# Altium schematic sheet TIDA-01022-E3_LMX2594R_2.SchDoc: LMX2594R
size 431 x 279 mm; Date: Not shown in title block; ApprovedBy: Not shown in title block; CheckedBy: Not shown in title block; Author: Not shown in title block; CompanyName: Not shown in title block; DrawnBy: Avinash N; Engineer: Not shown in title block; Organization: Not shown in title block; Address1: Not shown in title block; Address2: Not shown in title block; Address3: Not shown in title block; Address4: Not shown in title block; DocumentNumber: 1; Revision: Use project parameter SCH_Rev; SheetNumber: 11; SheetTotal: 26; PageSetup: Record=PageOptions¦CenterHorizontal=True¦CenterVertical=True¦PrintScale=0.59¦XCorrection=1.00¦YCorrection=1.00¦PrintKind=0¦BorderSize=5000000¦LeftOffset=0¦BottomOffset=0¦Orientation=2¦PaperLength=1000¦PaperWidth=1000¦Scale=100¦PaperSource=15¦PrintQuality=600¦MediaType=1¦DitherType=10¦PrintScaleMode=1¦PaperKind=Letter
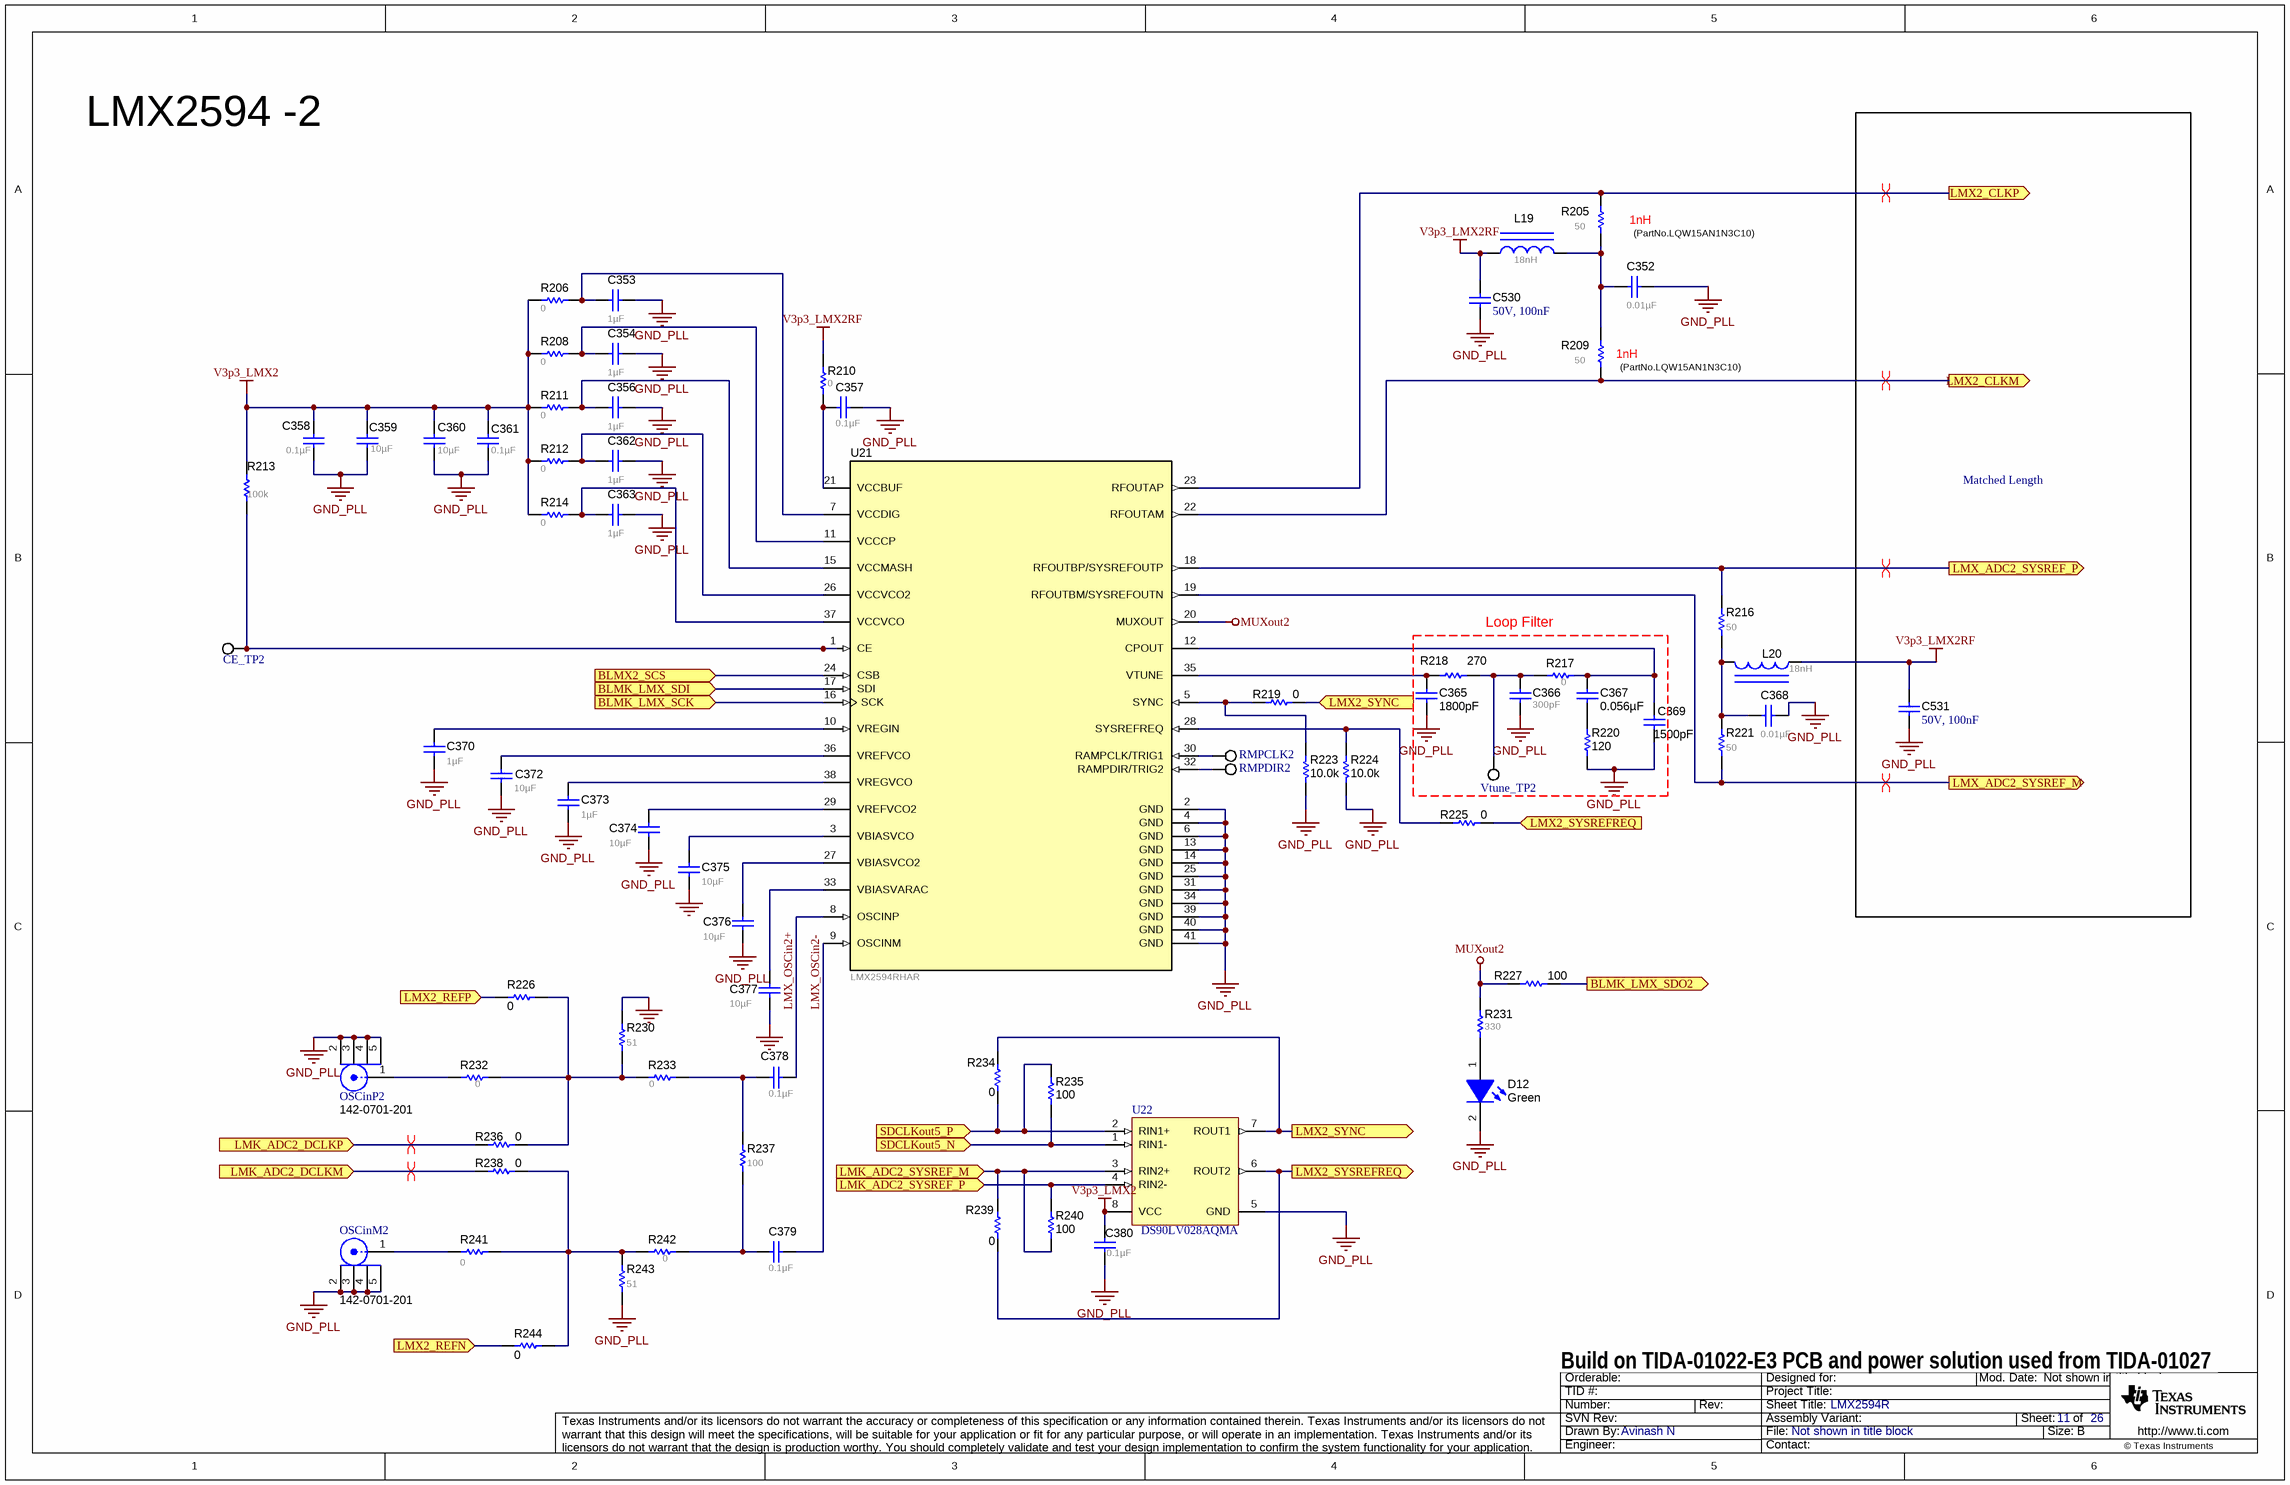
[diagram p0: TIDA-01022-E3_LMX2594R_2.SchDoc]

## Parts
C352  ValueDisplayed: 0.01µF  [0402_065]  (hidden comment: 520L103KT16T)
C353  ValueDisplayed: 1µF  [0603]  (hidden comment: C1608X7R1C105K080AC)
C354  ValueDisplayed: 1µF  [0603L]  (hidden comment: C1608X7R1C105K080AC)
C356  ValueDisplayed: 1µF  [0603L]  (hidden comment: C1608X7R1C105K080AC)
C357  ValueDisplayed: 0.1µF  [0603L]  (hidden comment: 0603YC104JAT2A)
C358  ValueDisplayed: 0.1µF  [0603]  (hidden comment: 0603YC104JAT2A)
C359  ValueDisplayed: 10µF  [0805]  (hidden comment: C0805C106K8PACTU)
C360  ValueDisplayed: 10µF  [0805]  (hidden comment: C0805C106K8PACTU)
C361  ValueDisplayed: 0.1µF  [0603]  (hidden comment: 0603YC104JAT2A)
C362  ValueDisplayed: 1µF  [0603]  (hidden comment: C1608X7R1C105K080AC)
C363  ValueDisplayed: 1µF  [0603]  (hidden comment: C1608X7R1C105K080AC)
C365  ValueDisplayed: 1800pF  [0603]  (hidden comment: GRM1885C1H182JA01D)
C366  ValueDisplayed: 300pF  [0603]  (hidden comment: GRM1885C2A301JA01D)
C367  ValueDisplayed: 0.056µF  [0603]  (hidden comment: C0603C563J4RACTU)
C368  ValueDisplayed: 0.01µF  [0402_065]  (hidden comment: 520L103KT16T)
C369  ValueDisplayed: 1500pF  [0603]  (hidden comment: 06031C152JAT2A)
C370  ValueDisplayed: 1µF  [0603]  (hidden comment: C1608X7R1C105K080AC)
C372  ValueDisplayed: 10µF  [0603]  (hidden comment: C1608X5R1A106M080AC)
C373  ValueDisplayed: 1µF  [0603]  (hidden comment: C1608X7R1C105K080AC)
C374  ValueDisplayed: 10µF  [0603]  (hidden comment: C1608X5R1A106M080AC)
C375  ValueDisplayed: 10µF  [0603]  (hidden comment: C1608X5R1A106M080AC)
C376  ValueDisplayed: 10µF  [0603]  (hidden comment: C1608X5R1A106M080AC)
C377  ValueDisplayed: 10µF  [0603]  (hidden comment: C1608X5R1A106M080AC)
C378  ValueDisplayed: 0.1µF  [0603L]  (hidden comment: 0603YC104JAT2A)
C379  ValueDisplayed: 0.1µF  [0603L]  (hidden comment: 0603YC104JAT2A)
C380  ValueDisplayed: 0.1µF  [0603]  (hidden comment: 0603YC104JAT2A)
C530  50V, 100nF  [0603_1.6x0.8x0.8mm_Reflow Soldering]
C531  50V, 100nF  [0603_1.6x0.8x0.8mm_Reflow Soldering]
CE_TP2  5002  [Keystone5002]  (value not drawn)
D12  value Green  [LTST-C191_Green]  (hidden comment: LTST-C191TGKT)
L19  ValueDisplayed: 18nH  [IND_LQG15H]  (hidden comment: LQG15HS18NJ02D)
L20  ValueDisplayed: 18nH  [IND_LQG15H]  (hidden comment: LQG15HS18NJ02D)
OSCinM2  142-0701-201  [Johnson_142-0701-20x]
OSCinP2  142-0701-201  [Johnson_142-0701-20x]
R205  ValueDisplayed: 50  [0402L]  (hidden comment: FC0402E50R0BST1)
R206  value 0  [0603]  (hidden comment: CRCW06030000Z0EA)
R208  value 0  [0603L]  (hidden comment: CRCW06030000Z0EA)
R209  ValueDisplayed: 50  [0402L]  (hidden comment: FC0402E50R0BST1)
R210  value 0  [0603L]  (hidden comment: CRCW06030000Z0EA)
R211  value 0  [0603L]  (hidden comment: CRCW06030000Z0EA)
R212  value 0  [0603]  (hidden comment: CRCW06030000Z0EA)
R213  ValueDisplayed: 100k  [0603]  (hidden comment: CRCW0603100KJNEA)
R214  value 0  [0603]  (hidden comment: CRCW06030000Z0EA)
R216  ValueDisplayed: 50  [0402L]  (hidden comment: FC0402E50R0BST1)
R217  ValueDisplayed: 0  [0603]  (hidden comment: CRCW06030000Z0EA)
R218  ValueDisplayed: 270  [0603]  (hidden comment: RC0603JR-07270RL)
R219  ValueDisplayed: 0  [0402]  (hidden comment: CRCW04020000Z0ED)
R220  ValueDisplayed: 120  [0603]  (hidden comment: RT0603DRE07120RL)
R221  ValueDisplayed: 50  [0402L]  (hidden comment: FC0402E50R0BST1)
R223  ValueDisplayed: 10.0k  [0402]  (hidden comment: CRCW040210K0DHEDP)
R224  ValueDisplayed: 10.0k  [0402]  (hidden comment: CRCW040210K0DHEDP)
R225  ValueDisplayed: 0  [0402]  (hidden comment: CRCW04020000Z0ED)
R226  ValueDisplayed: 0  [0402]  (hidden comment: CRCW04020000Z0ED)
R227  ValueDisplayed: 100  [0603]  (hidden comment: CRCW0603100RFKEA)
R230  ValueDisplayed: 51  [0603]  (hidden comment: CRCW060351R0JNEA)
R231  value 330  [0603]  (hidden comment: RC0603JR-07330RL)
R232  ValueDisplayed: 0  [0603]  (hidden comment: CRCW06030000Z0EA)
R233  ValueDisplayed: 0  [0603]  (hidden comment: CRCW06030000Z0EA)
R234  ValueDisplayed: 0  [0402]  (hidden comment: CRCW04020000Z0ED)
R235  ValueDisplayed: 100  [0402]  (hidden comment: CRCW0402100RJNED)
R236  ValueDisplayed: 0  [0402]  (hidden comment: CRCW04020000Z0ED)
R237  ValueDisplayed: 100  [0603L]  (hidden comment: CRCW0603100RFKEA)
R238  ValueDisplayed: 0  [0402]  (hidden comment: CRCW04020000Z0ED)
R239  ValueDisplayed: 0  [0402]  (hidden comment: CRCW04020000Z0ED)
R240  ValueDisplayed: 100  [0402]  (hidden comment: CRCW0402100RJNED)
R241  ValueDisplayed: 0  [0603]  (hidden comment: CRCW06030000Z0EA)
R242  ValueDisplayed: 0  [0603]  (hidden comment: CRCW06030000Z0EA)
R243  ValueDisplayed: 51  [0603]  (hidden comment: CRCW060351R0JNEA)
R244  ValueDisplayed: 0  [0402]  (hidden comment: CRCW04020000Z0ED)
RMPCLK2  5002  [Keystone5002]  (value not drawn)
RMPDIR2  5002  [Keystone5002]  (value not drawn)
U21  LMX2594RHAR  [RHA0040A]
U22  DS90LV028AQMA  [M08A_N]
Vtune_TP2  5002  [Keystone5002]  (value not drawn)

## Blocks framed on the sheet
Matched Length: C531
Loop Filter: C365-C367 C369 R217 R218 R220 Vtune_TP2

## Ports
BLMK_LMX_SCK (in), BLMK_LMX_SDI (in), BLMK_LMX_SDO2 (out), BLMX2_SCS (in), LMK_ADC2_DCLKM (in), LMK_ADC2_DCLKP (in), LMK_ADC2_SYSREF_M (in), LMK_ADC2_SYSREF_P (in), LMX2_CLKM (out), LMX2_CLKP (out), LMX2_REFN (in), LMX2_REFP (in), LMX2_SYNC (in), LMX2_SYNC (out), LMX2_SYSREFREQ (in), LMX2_SYSREFREQ (out), LMX_ADC2_SYSREF_M (out), LMX_ADC2_SYSREF_P (out), SDCLKout5_N (in), SDCLKout5_P (in)

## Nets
GND_PLL: C352.1 C353.1 C354.1 C356.2 C357.1 C358.1 C359.1 C360.1 C361.1 C362.1 C363.1 C365.1 C366.2 C368.1 C369.2 C370.1 C372.2 C373.1 C374.2 C375.2 C376.1 C377.1 C380.1 C530.2 C531.2 D12.2(K) OSCinM2.2 OSCinM2.3 OSCinM2.4 OSCinM2.5 OSCinP2.2 OSCinP2.3 OSCinP2.4 OSCinP2.5 R220.2 R223.2 R224.2 R230.2 R243.1 U21.2(GND) U21.4(GND) U21.6(GND) U21.13(GND) U21.14(GND) U21.25(GND) U21.31(GND) U21.34(GND) U21.39(GND) U21.40(GND) U21.41(GND) U22.5(GND)
MUXout2: R227.1 R231.2 U21.20(MUXOUT)
V3p3_LMX2: C358.2 C359.2 C360.2 C361.2 C380.2 R206.1 R208.1 R211.1 R212.2 R213.1 R214.2 U22.8(VCC)
V3p3_LMX2RF: C530.1 C531.1 L19.1 L20.1 R210.1
BLMK_LMX_SCK: U21.16(SCK) ; port BLMK_LMX_SCK
BLMK_LMX_SDI: U21.17(SDI) ; port BLMK_LMX_SDI
BLMK_LMX_SDO2: R227.2 ; port BLMK_LMX_SDO2
BLMX2_SCS: U21.24(CSB) ; port BLMX2_SCS
LMK_ADC2_DCLKM: R238.1 ; port LMK_ADC2_DCLKM
LMK_ADC2_DCLKP: R236.1 ; port LMK_ADC2_DCLKP
LMK_ADC2_SYSREF_M: R239.1 R240.1 U22.3(RIN2+) ; port LMK_ADC2_SYSREF_M
LMK_ADC2_SYSREF_P: R240.2 U22.4(RIN2-) ; port LMK_ADC2_SYSREF_P
LMX2_CLKM: R209.1 U21.22(RFOUTAM) ; port LMX2_CLKM
LMX2_CLKP: R205.1 U21.23(RFOUTAP) ; port LMX2_CLKP
LMX2_REFN: R244.1 ; port LMX2_REFN
LMX2_REFP: R226.2 ; port LMX2_REFP
LMX2_SYNC: R219.2 R234.1 U22.7(ROUT1) ; port LMX2_SYNC
LMX2_SYSREFREQ: R225.2 R239.2 U22.6(ROUT2) ; port LMX2_SYSREFREQ
LMX_ADC2_SYSREF_M: R221.1 U21.19(RFOUTBM/SYSREFOUTN) ; port LMX_ADC2_SYSREF_M
LMX_ADC2_SYSREF_P: R216.2 U21.18(RFOUTBP/SYSREFOUTP) ; port LMX_ADC2_SYSREF_P
LMX_OSCin2+: C378.2 U21.8(OSCINP)
LMX_OSCin2-: C379.2 U21.9(OSCINM)
SDCLKout5_N: R235.1 U22.1(RIN1-) ; port SDCLKout5_N
SDCLKout5_P: R234.2 R235.2 U22.2(RIN1+) ; port SDCLKout5_P
NetC352_2: C352.2 L19.2 R205.2 R209.2
NetC353_2: C353.2 R206.2 U21.7(VCCDIG)
NetC354_2: C354.2 R208.2 U21.11(VCCCP)
NetC356_1: C356.1 R211.2 U21.15(VCCMASH)
NetC357_2: C357.2 R210.2 U21.21(VCCBUF)
NetC362_2: C362.2 R212.1 U21.26(VCCVCO2)
NetC363_2: C363.2 R214.1 U21.37(VCCVCO)
NetC365_2: C365.2 R218.1 U21.35(VTUNE)
NetC366_1: C366.1 R217.2 R218.2 Vtune_TP2.1
NetC367_1: C367.1 C369.1 R217.1 U21.12(CPOUT)
NetC367_2: C367.2 R220.1
NetC368_2: C368.2 L20.2 R216.1 R221.2
NetC370_2: C370.2 U21.10(VREGIN)
NetC372_1: C372.1 U21.36(VREFVCO)
NetC373_2: C373.2 U21.38(VREGVCO)
NetC374_1: C374.1 U21.29(VREFVCO2)
NetC375_1: C375.1 U21.3(VBIASVCO)
NetC376_2: C376.2 U21.27(VBIASVCO2)
NetC377_2: C377.2 U21.33(VBIASVARAC)
NetC378_1: C378.1 R233.2 R237.2
NetC379_1: C379.1 R237.1 R242.1
NetCE_TP2_1: CE_TP2.1 R213.2 U21.1(CE)
NetD12_1: D12.1(A) R231.1
NetOSCinM2_1: OSCinM2.1 R241.1
NetOSCinP2_1: OSCinP2.1 R232.1
NetR219_1: R219.1 R223.1 U21.5(SYNC)
NetR224_1: R224.1 R225.1 U21.28(SYSREFREQ)
NetR226_1: R226.1 R230.1 R232.2 R233.1 R236.2
NetR238_2: R238.2 R241.2 R242.2 R243.2 R244.2
NetRMPCLK2_1: RMPCLK2.1 U21.30(RAMPCLK/TRIG1)
NetRMPDIR2_1: RMPDIR2.1 U21.32(RAMPDIR/TRIG2)

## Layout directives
differential pair: LMK_ADC2_DCLKM, LMK_ADC2_DCLKP, LMX2_CLKM, LMX2_CLKP, LMX_ADC2_SYSREF_M, LMX_ADC2_SYSREF_P

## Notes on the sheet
- LMX2594 -2
- (near R205) 1nH
- (PartNo.LQW15AN1N3C10)
- (near R209) 1nH
- (near R209) (PartNo.LQW15AN1N3C10)
- Build on TIDA-01022-E3 PCB and power solution used from TIDA-01027

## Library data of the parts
C352 C368 = 520L103KT16T: CAP, CERM, 0.01 µF, 16 V, +/- 10%, X7R, 0402; Manufacturer: AT Ceramics; Polarized: N; CompType: Capacitor; Value: 0.01uF; U/M: EA; Cap_F: 0.00000001; Tolerance_%: 10; Value1: Unknown; VDC_V: 16; Value2: 16V; TaMin_C: -55; TaMax_C: 125; Cap_Case: 0402; AEC Category: Q200; SizeArea_mm2: 0.5; SizeAreaWB_mm2: 3; SizeX_mm: 1; SizeZ_mm: 0.65
C353 C362 C363 = C1608X7R1C105K080AC: CAP, CERM, 1 µF, 16 V, +/- 10%, X7R, 0603; Manufacturer: TDK; ESR_ohm: 0.0057; Polarized: N; TaMax_C: 125; TaMin_C: -55; Tolerance_%: 10; VDC_V: 16; Cap_F: 0.000001; CompType: Capacitor; Value: 1uF; Value1: 0.0057 ohm; Value2: 16V; U/M: EA; SizeArea_mm2: 1.28; SizeAreaWB_mm2: 4.68; SizeX_mm: 1.6; SizeY_mm: 0.8; SizeZ_mm: 1; AEC Category: Q200
C354 C356 = C1608X7R1C105K080AC: CAP, CERM, 1 µF, 16 V, +/- 10%, X7R, 0603; Manufacturer: TDK; Cap_Case: 0603; ESR_ohm: 0.0057; Polarized: N; TaMax_C: 125; TaMin_C: -55; Tolerance_%: 10; VDC_V: 16; Cap_F: 0.000001; CompType: Capacitor; Value: 1uF; Value1: 0.0057 ohm; Value2: 16V; U/M: EA; SizeArea_mm2: 1.28; SizeAreaWB_mm2: 4.68; SizeX_mm: 1.6; SizeY_mm: 0.8; SizeZ_mm: 1; AEC Category: Q200
C357 C378 C379 = 0603YC104JAT2A: CAP, CERM, 0.1uF, 16V, +/-5%, X7R, 0603; Manufacturer: AVX; Cap_Case: 0603; ESR_Ohm: 0.039; Polarized: N; TaMax_C: 125; TaMin_C: -55; Tolerance_%: 5; VDC_V: 16; Cap_F: 0.0000001; CompType: Capacitor; Value1: 0.039 ohm; U/M: EA
C358 C361 C380 = 0603YC104JAT2A: CAP, CERM, 0.1uF, 16V, +/-5%, X7R, 0603; Manufacturer: AVX; ESR_Ohm: 0.039; Polarized: N; TaMax_C: 125; TaMin_C: -55; Tolerance_%: 5; VDC_V: 16; Cap_F: 0.0000001; CompType: Capacitor; Value1: 0.039 ohm; U/M: EA
C359 C360 = C0805C106K8PACTU: CAP, CERM, 10uF, 10V, +/-10%, X5R, 0805; Manufacturer: Kemet; ESR_Ohm: 0.003; IRMS_A: 11.43; Polarized: N; TaMax_C: 85; TaMin_C: -55; Tolerance_%: 10; Cap_F: 0.00001; CompType: Capacitor; U/M: EA; Value1: 0.003 ohm
C365 = GRM1885C1H182JA01D: CAP, CERM, 1800 pF, 50 V, +/- 5%, C0G/NP0, 0603; Manufacturer: MuRata; Polarized: N; TaMax_C: 125; TaMin_C: -55; Tolerance_%: 5; VDC_V: 50; Cap_F: 0.0000000018; CompType: Capacitor; Value: 1800pF; Value1: Unknown; Value2: 50V; U/M: EA; SizeArea_mm2: 1.28; SizeAreaWB_mm2: 4.68; SizeX_mm: 1.6; SizeY_mm: 0.8; SizeZ_mm: 1; AEC Category: Q200
C366 = GRM1885C2A301JA01D: CAP, CERM, 300pF, 100V, +/-5%, C0G/NP0, 0603; Manufacturer: MuRata; Polarized: N; TaMax_C: 125; TaMin_C: -55; Tolerance_%: 5; VDC_V: 100; Cap_F: 0.0000000003; CompType: Capacitor; Value1: Unknown; U/M: EA
C367 = C0603C563J4RACTU: CAP, CERM, 0.056 µF, 16 V, +/- 5%, X7R, 0603; Manufacturer: Kemet; Polarized: N; TaMax_C: 125; TaMin_C: -55; Tolerance_%: 5; VDC_V: 16; Cap_F: 0.000000056; CompType: Capacitor; Value: 0.056uF; Value1: Unknown; Value2: 16V; U/M: EA; AEC Category: Q200; SizeArea_mm2: 1.28; SizeAreaWB_mm2: 4.68; SizeX_mm: 1.6; SizeY_mm: 0.8; SizeZ_mm: 1
C369 = 06031C152JAT2A: CAP, CERM, 1500 pF, 100 V, +/- 5%, X7R, 0603; Manufacturer: AVX; ESR_ohm: 0.229; Polarized: N; TaMax_C: 125; TaMin_C: -55; Tolerance_%: 5; VDC_V: 100; Cap_F: 0.0000000015; CompType: Capacitor; Value: 1500pF; Value1: 0.229 ohm; Value2: 100V; U/M: EA; AEC Category: Q200; SizeArea_mm2: 1.28; SizeAreaWB_mm2: 4.68; SizeX_mm: 1.6; SizeY_mm: 0.8; SizeZ_mm: 1
C370 = C1608X7R1C105K080AC: CAP, CERM, 1 µF, 16 V, +/- 10%, X7R, 0603; Manufacturer: TDK; Polarized: N; CompType: Capacitor; Value: 1uF; U/M: EA; Cap_F: 0.000001; Tolerance_%: 10; ESR_ohm: 0.0057; Value1: 0.0057 ohm; VDC_V: 16; Value2: 16V; TaMin_C: -55; TaMax_C: 125; AEC Category: Q200
C372 C374-C377 = C1608X5R1A106M080AC: CAP, CERM, 10 µF, 10 V, +/- 20%, X5R, 0603; Manufacturer: TDK; ESR_ohm: 0.0078; IRMS_A: 1.85; Polarized: N; TaMax_C: 85; TaMin_C: -55; Tolerance_%: 20; VDC_V: 10; Cap_F: 0.00001; CompType: Capacitor; Value: 10uF; U/M: EA; Value1: 0.0078 ohm; Value2: 10V; AEC Category: Q200
C373 = C1608X7R1C105K080AC: CAP, CERM, 1 µF, 16 V, +/- 10%, X7R, 0603; Manufacturer: TDK; ESR_ohm: 0.0057; Polarized: N; TaMax_C: 125; TaMin_C: -55; Tolerance_%: 10; VDC_V: 16; Cap_F: 0.000001; CompType: Capacitor; Value: 1uF; U/M: EA; Value1: 0.0057 ohm; Value2: 16V; AEC Category: Q200
C530 C531 = 885012206095: WCAP-CSGP Ceramic Capacitors, 0603, X7R, 50V, 100nF; Rated Voltage: 50V DC
CE_TP2 RMPCLK2 RMPDIR2 Vtune_TP2 = 5002: Test Point, Miniature, White, TH; Manufacturer: Keystone; CompType: Test Point Loop; ContactFinish: Silver; Green_Lifecycle: Active; Green_REACh: Passed
D12 = LTST-C191TGKT: LED, Green, SMD; Manufacturer: Lite-On; Type: InGaN; Vf_V: 3.2; Value2: 3.2V; Io_A: 0.02; Value1: W; U/M: EA
L19 L20 = LQG15HS18NJ02D: Inductor, Multilayer, Air Core, 18 nH, 0.3 A, 0.36 ohm, SMD; Manufacturer: MuRata; Value: 18nH; Ind_H: 18.0E-9; Imax_A: 0.3; Irms: 0.3A @ C rise; Isat: 0.3A @ % inductance drop; DCR_ohm: 0.36; Value2: 0.3A; AEC Category: Q200
OSCinM2 OSCinP2 = 142-0701-201: Connector, TH, SMA; Manufacturer: Emerson Network Power; SymbolCreator: X0208326
R205 R209 R216 R221 = FC0402E50R0BST1: RES, 50, 0.1%, 0.05 W, 0402; Manufacturer: Vishay-Dale; CompType: Resistor; Value: 50; Value_Code: 50R0; Tolerance_%: 0.1; Power_W: 0.05; Value2: 0.05W; TempCo: 25 ppm/C; U/M: EA; SizeArea_mm2: 0.5; SizeX_mm: 1; SizeZ_mm: 0.6; AEC Category: Q200; AEC Qualified: N
R206 R208 R210-R212 R214 = CRCW06030000Z0EA: RES, 0 ohm, 5%, 0.1W, 0603; Manufacturer: Vishay-Dale; CompType: Resistor; Tolerance_%: 5; VDC_V: 75; Power_W: 0.1; U/M: EA; Value_Code: 0000; EIA_Code: E24
R213 = CRCW0603100KJNEA: RES, 100 k, 5%, 0.1 W, 0603; Manufacturer: Vishay-Dale; CompType: Resistor; Tolerance_%: 5; VDC_V: 75; Power_W: 0.1; Res_ohm: 100000; Value: 100k; U/M: EA; Value2: 0.1W; EIA_Code: E24; TempCo: 200 ppm/C; SizeArea_mm2: 1.28; SizeX_mm: 1.6; SizeY_mm: 0.8; SizeZ_mm: 1; AEC Category: Q200
R217 R232 R233 R241 R242 = CRCW06030000Z0EA: RES, 0, 5%, 0.1 W, 0603; Manufacturer: Vishay-Dale; CompType: Resistor; Tolerance_%: 5; VDC_V: 75; Power_W: 0.1; Value: 0; U/M: EA; Value_Code: 0000; Value2: 0.1W; EIA_Code: E24; TempCo: 200 ppm/C; SizeArea_mm2: 1.28; SizeX_mm: 1.6; SizeY_mm: 0.8; SizeZ_mm: 1; AEC Category: Q200
R218 = RC0603JR-07270RL: RES, 270, 5%, 0.1 W, 0603; Manufacturer: Yageo America; CompType: Resistor; Tolerance_%: 5; VDC_V: 50; Power_W: 0.1; Value: 270; U/M: EA; Value_Code: 270R; Value2: 0.1W; EIA_Code: E24; TempCo: 100 ppm/C; SizeArea_mm2: 1.28; SizeX_mm: 1.6; SizeY_mm: 0.8; SizeZ_mm: 1; AEC Category: Q200
R219 R225 R234 R236 R238 R239 = CRCW04020000Z0ED: RES, 0, 5%, 0.063 W, 0402; Manufacturer: Vishay-Dale; CompType: Resistor; Value: 0; Value_Code: 0000; Tolerance_%: 5; Power_W: 0.063; Value2: 0.063W; VDC_V: 50; TempCo: 200 ppm/C; SizeArea_mm2: 0.5; SizeX_mm: 1; SizeZ_mm: 0.6; EIA_Code: E24; U/M: EA; AEC Category: Q200
R220 = RT0603DRE07120RL: RES, 120, 0.5%, 0.1 W, 0603; Manufacturer: Yageo America; CompType: Resistor; Tolerance_%: 0.5; VDC_V: 75; Power_W: 0.1; Value: 120; U/M: EA; Value_Code: 120R; Value2: 0.1W; TempCo: 50 ppm/C; EIA_Code: E192; SizeArea_mm2: 1.28; SizeX_mm: 1.6; SizeY_mm: 0.8; SizeZ_mm: 1; AEC Category: Q200
R223 R224 = CRCW040210K0DHEDP: RES, 10.0 k, 0.5%, 0.063 W, 0402; Manufacturer: Vishay-Dale; CompType: Resistor; Value: 10.0k; Res_ohm: 10000; Value_Code: 10k0; Tolerance_%: 0.5; Power_W: 0.063; Value2: 0.063W; VDC_V: 50; TempCo: 50 ppm/C; SizeX_mm: 1; SizeZ_mm: 0.6; EIA_Code: E192; U/M: EA; AEC Category: Q200
R226 R244 = CRCW04020000Z0ED: RES, 0, 5%, 0.063 W, 0402; Manufacturer: Vishay-Dale; CompType: Resistor; Tolerance_%: 5; VDC_V: 50; Power_W: 0.063; Value: 0; U/M: EA; Value_Code: 0000; Value2: 0.063W; EIA_Code: E24; TempCo: 200 ppm/C; SizeArea_mm2: 0.5; SizeX_mm: 1; SizeZ_mm: 0.6; AEC Category: Q200
R227 = CRCW0603100RFKEA: RES, 100, 1%, 0.1 W, 0603; Manufacturer: Vishay-Dale; CompType: Resistor; Value: 100; Value_Code: 100R; Tolerance_%: 1; Power_W: 0.1; Value2: 0.1W; VDC_V: 75; TempCo: 100 ppm/C; SizeArea_mm2: 1.28; SizeX_mm: 1.6; SizeY_mm: 0.8; EIA_Code: E96; U/M: EA; AEC Category: Q200
R230 R243 = CRCW060351R0JNEA: RES, 51, 5%, 0.1 W, 0603; Manufacturer: Vishay-Dale; CompType: Resistor; Value: 51; Value_Code: 51R0; Tolerance_%: 5; Power_W: 0.1; Value2: 0.1W; VDC_V: 75; TempCo: 200 ppm/C; EIA_Code: E24; U/M: EA; SizeArea_mm2: 1.28; SizeX_mm: 1.6; SizeY_mm: 0.8; SizeZ_mm: 1; AEC Category: Q200
R231 = RC0603JR-07330RL: RES, 330 ohm, 5%, 0.1W, 0603; Manufacturer: Yageo America; CompType: Resistor; Tolerance_%: 5; VDC_V: 50; Power_W: 0.1; U/M: EA; Value_Code: 330R; EIA_Code: E24
R235 R240 = CRCW0402100RJNED: RES, 100, 5%, 0.063 W, 0402; Manufacturer: Vishay-Dale; CompType: Resistor; Value: 100; Value_Code: 100R; Tolerance_%: 5; Power_W: 0.063; Value2: 0.063W; VDC_V: 50; TempCo: 200 ppm/C; SizeArea_mm2: 0.5; SizeX_mm: 1; SizeZ_mm: 0.6; EIA_Code: E24; U/M: EA; AEC Category: Q200
R237 = CRCW0603100RFKEA: RES, 100, 1%, 0.1 W, 0603; Manufacturer: Vishay-Dale; CompType: Resistor; Tolerance_%: 1; VDC_V: 75; Power_W: 0.1; Value: 100; U/M: EA; Value_Code: 100R; Value2: 0.1W; EIA_Code: E96; TempCo: 100 ppm/C; SizeArea_mm2: 1.28; SizeX_mm: 1.6; SizeY_mm: 0.8; AEC Category: Q200
U21 = LMX2594RHAR: High Performance, Wideband PLLatinum RF Synthesizer, RHA0040A (VQFN-40); Alternate PartNumber: LMX2594RHAT; Manufacturer: Texas Instruments; SymbolCreator: Altium; SizeArea_mm2: 36; SizeAreaWB_mm2: 64; SizeX_mm: 6; SizeZ_mm: 1; CompType: IC; U/M: EA
U22 = DS90LV028AQMA: Automotive LVDS Dual Differential Line Receiver, 8-pin Narrow SOIC; Manufacturer: Texas Instruments; PackageTopMarking: NSZXTT*90LV0*28AQM; PowerWise: N; CompType: Interface IC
